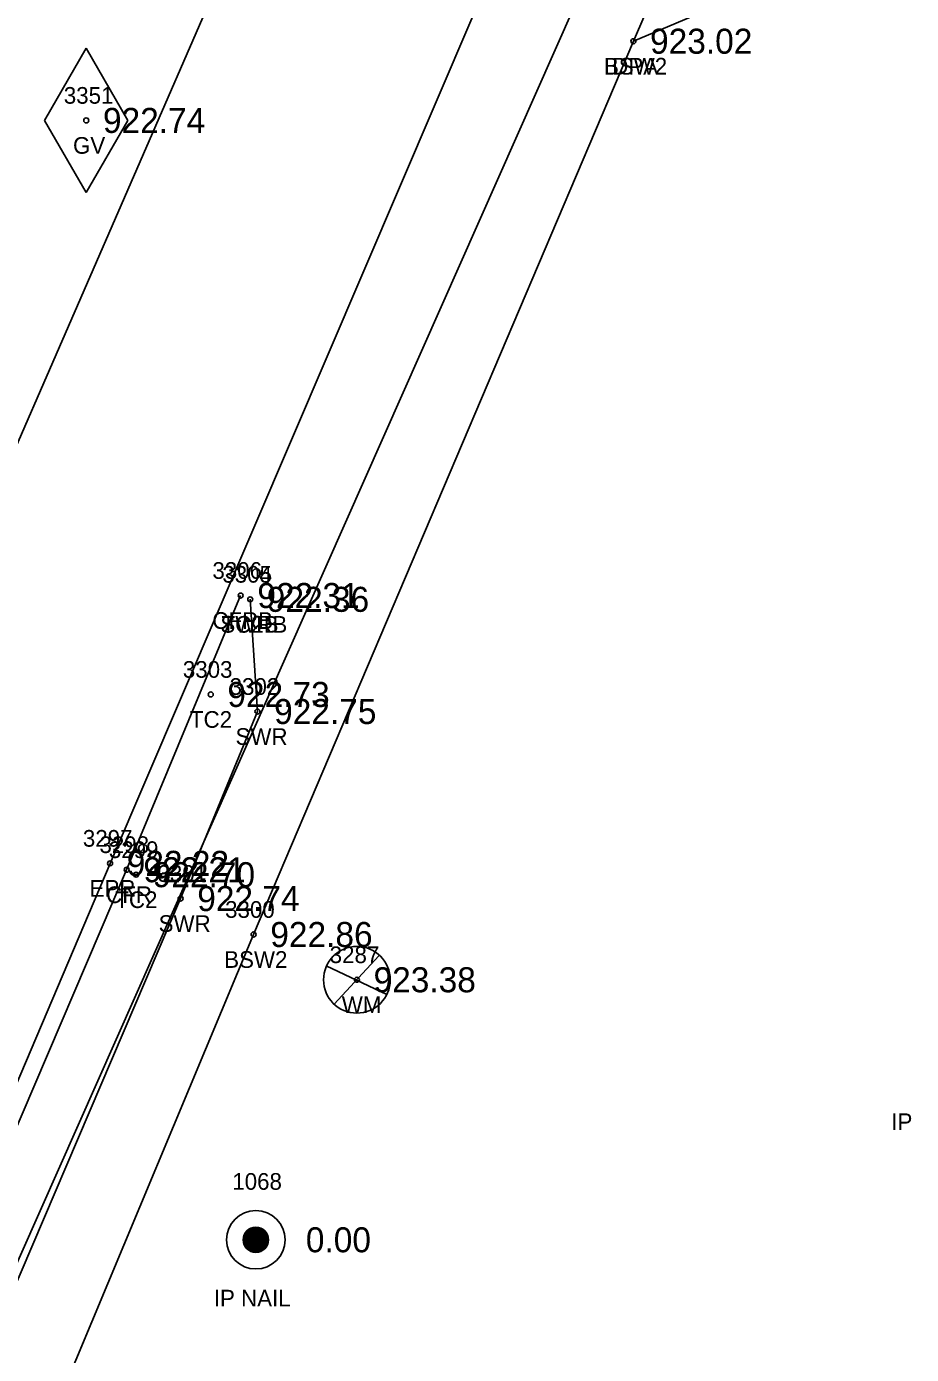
# Model space of a CAD drawing. Extents: x 1575382 to 1578175, y 1099175 to 1101955.
# Drawn here: x 1577161 to 1577214.1, y 1100867.9 to 1100947.5 of the extents above; entities that cross this region are included whole.
import ezdxf

# ---------------------------------------------------------------- set-up
doc = ezdxf.new("R2010")
doc.units = 0
for name, color, linetype in [('RD_EX_Conc', 7, 'Continuous'), ('RD_EX_Conc_txCode', 7, 'Continuous'), ('RD_EX_DR_Pipe', 7, 'Continuous'), ('RD_EX_Driveway', 7, 'Continuous'), ('RD_EX_Driveway_txCode', 7, 'Continuous'), ('RD_EX_DV_Prop_txCode', 7, 'Continuous'), ('RD_EX_DV_PropPin', 7, 'Continuous'), ('RD_EX_Road', 7, 'Continuous'), ('RD_EX_Road_txCode', 7, 'Continuous'), ('RD_EX_TX_Conc_ELEV', 7, 'Continuous'), ('RD_EX_TX_Driveway_ELEV', 7, 'Continuous'), ('RD_EX_TX_DV_Prop_ELEV', 7, 'Continuous'), ('RD_EX_TX_Road_ELEV', 7, 'Continuous'), ('RD_EX_TX_UT_ELEV', 7, 'Continuous'), ('RD_EX_UT', 7, 'Continuous'), ('RD_EX_UT_txCode', 7, 'Continuous'), ('RD_HC_Cl', 7, 'Continuous'), ('RD_SMD_Locator', 7, 'Continuous')]:
    doc.layers.add(name, color=color, linetype=linetype)

msp = doc.modelspace()

# ---------------------------------------------------------------- linework, layer by layer
at = {"layer": 'RD_EX_Conc'}
for points in [[(1577055.154, 1100662.638), (1577085.172, 1100716.01), (1577085.172, 1100716.01), (1577107.371, 1100755.865), (1577118.9, 1100776.662), (1577132.782, 1100800.808), (1577154.825, 1100846.618), (1577163.043, 1100865.238), (1577174.665, 1100893.053), (1577197.436, 1100946.62), (1577213.904, 1100984.916), (1577231.037, 1101024.713)], [(1577129.98, 1100812.481), (1577147.365, 1100850.909), (1577167.052, 1100896.938), (1577173.888, 1100913.381)], [(1577132.717, 1100811.321), (1577150.445, 1100848.795), (1577170.285, 1100895.209), (1577174.895, 1100906.424), (1577174.458, 1100913.152)]]:
    msp.add_lwpolyline(points, dxfattribs=at)
at = {"layer": 'RD_EX_DR_Pipe'}
msp.add_lwpolyline([(1577139.994, 1100787.337), (1577129.779, 1100804.197), (1577129.779, 1100804.197), (1577232.824, 1101036.463), (1577232.824, 1101036.463), (1577240.152, 1101052.982)], dxfattribs=at)
at = {"layer": 'RD_EX_Driveway'}
msp.add_lwpolyline([(1577197.436, 1100946.62), (1577210.609, 1100952.199), (1577244.847, 1100927.029)], dxfattribs=at)
at = {"layer": 'RD_EX_DV_PropPin'}
for p, q in [((1577174.201, 1100874.272), (1577174.201, 1100875.22)), ((1577174.236, 1100874.231), (1577174.236, 1100875.261)), ((1577174.271, 1100874.195), (1577174.271, 1100875.297)), ((1577174.306, 1100874.164), (1577174.306, 1100875.328)), ((1577174.341, 1100874.136), (1577174.341, 1100875.356)), ((1577174.377, 1100874.111), (1577174.377, 1100875.38)), ((1577174.412, 1100874.09), (1577174.412, 1100875.402)), ((1577174.447, 1100874.07), (1577174.447, 1100875.422)), ((1577174.482, 1100874.053), (1577174.482, 1100875.439)), ((1577174.517, 1100874.038), (1577174.517, 1100875.453)), ((1577174.552, 1100874.025), (1577174.552, 1100875.466)), ((1577174.587, 1100874.014), (1577174.587, 1100875.477)), ((1577174.622, 1100874.005), (1577174.622, 1100875.487)), ((1577174.657, 1100873.998), (1577174.657, 1100875.494)), ((1577174.692, 1100873.992), (1577174.692, 1100875.5)), ((1577174.727, 1100873.988), (1577174.727, 1100875.504)), ((1577174.762, 1100873.986), (1577174.762, 1100875.506)), ((1577174.797, 1100873.985), (1577174.797, 1100875.507)), ((1577174.832, 1100873.986), (1577174.832, 1100875.506)), ((1577174.867, 1100873.988), (1577174.867, 1100875.504)), ((1577174.902, 1100873.992), (1577174.902, 1100875.5)), ((1577174.937, 1100873.998), (1577174.937, 1100875.494)), ((1577174.972, 1100874.005), (1577174.972, 1100875.487)), ((1577175.007, 1100874.014), (1577175.007, 1100875.477)), ((1577175.042, 1100874.025), (1577175.042, 1100875.466)), ((1577175.077, 1100874.038), (1577175.077, 1100875.453)), ((1577175.112, 1100874.053), (1577175.112, 1100875.439)), ((1577175.147, 1100874.07), (1577175.147, 1100875.422)), ((1577175.182, 1100874.09), (1577175.182, 1100875.402)), ((1577175.217, 1100874.111), (1577175.217, 1100875.38)), ((1577175.252, 1100874.136), (1577175.252, 1100875.356)), ((1577175.287, 1100874.164), (1577175.287, 1100875.328)), ((1577175.322, 1100874.195), (1577175.322, 1100875.297)), ((1577175.357, 1100874.231), (1577175.357, 1100875.261)), ((1577175.392, 1100874.272), (1577175.392, 1100875.22)), ((1577174.061, 1100874.55), (1577174.061, 1100874.942)), ((1577174.096, 1100874.448), (1577174.096, 1100875.044)), ((1577174.131, 1100874.376), (1577174.131, 1100875.115)), ((1577174.166, 1100874.319), (1577174.166, 1100875.172)), ((1577175.427, 1100874.319), (1577175.427, 1100875.172)), ((1577175.462, 1100874.376), (1577175.462, 1100875.115)), ((1577175.497, 1100874.448), (1577175.497, 1100875.044)), ((1577175.532, 1100874.55), (1577175.532, 1100874.942))]:
    msp.add_line(p, q, dxfattribs=at)
for radius in [1.75, 0.761]:
    msp.add_circle((1577174.797, 1100874.746), radius, dxfattribs=at)
at = {"layer": 'RD_EX_Road'}
msp.add_lwpolyline([(1577078.765, 1100718.331), (1577101.643, 1100758.923), (1577113.339, 1100780.089), (1577125.29, 1100804.69), (1577146.474, 1100851.246), (1577166.057, 1100897.319), (1577205.167, 1100988.676), (1577222.285, 1101028.955), (1577224.552, 1101032.022), (1577228.298, 1101034.471), (1577233.178, 1101036.099), (1577233.178, 1101036.099), (1577237.423, 1101035.839), (1577245.428, 1101032.846), (1577248.283, 1101031.553), (1577256.851, 1101026.156), (1577298.2, 1100997.596), (1577319.207, 1100982.295), (1577334.075, 1100971.377)], dxfattribs=at)
at = {"layer": 'RD_EX_UT'}
for p, q in [((1577162.131, 1100941.871), (1577164.631, 1100946.202)), ((1577164.631, 1100946.202), (1577167.131, 1100941.871)), ((1577162.131, 1100941.871), (1577164.631, 1100937.541)), ((1577164.631, 1100937.541), (1577167.131, 1100941.871)), ((1577179.023, 1100891.175), (1577182.654, 1100889.462)), ((1577179.504, 1100888.88), (1577182.172, 1100891.776))]:
    msp.add_line(p, q, dxfattribs=at)
msp.add_circle((1577180.856, 1100890.338), 2, dxfattribs=at)
at = {"layer": 'RD_HC_Cl'}
msp.add_line((1577114.032, 1100815.757), (1577364.891, 1101392.08), dxfattribs=at)
at = {"layer": 'RD_SMD_Locator'}
for centre in [(1577197.436, 1100946.62), (1577197.436, 1100946.62), (1577164.631, 1100941.871), (1577173.888, 1100913.381), (1577174.458, 1100913.152), (1577174.458, 1100913.152), (1577172.091, 1100907.448), (1577174.895, 1100906.424), (1577166.057, 1100897.319), (1577167.052, 1100896.938), (1577167.616, 1100896.64), (1577170.285, 1100895.209), (1577174.665, 1100893.053), (1577180.856, 1100890.338), (1577174.797, 1100874.746)]:
    msp.add_circle(centre, 0.15, dxfattribs=at)

# ---------------------------------------------------------------- texts
at = {"layer": 'RD_EX_Conc_txCode'}
for s, p in [('BSW2', (1577195.673, 1100944.62)), ('3306', (1577172.195, 1100914.381)), ('3304', (1577172.789, 1100914.152)), ('3305', (1577172.789, 1100914.152)), ('CFRB', (1577172.187, 1100911.381)), ('SWRB', (1577172.671, 1100911.152)), ('TC2B', (1577172.742, 1100911.152)), ('3303', (1577170.422, 1100908.448)), ('3302', (1577173.226, 1100907.424)), ('TC2', (1577170.847, 1100905.448)), ('SWR', (1577173.58, 1100904.424)), ('3298', (1577165.422, 1100897.938)), ('3299', (1577165.986, 1100897.64)), ('3301', (1577168.899, 1100896.209)), ('CFR', (1577165.824, 1100894.938)), ('TC2', (1577166.372, 1100894.64)), ('3300', (1577172.956, 1100894.053)), ('SWR', (1577168.97, 1100893.209)), ('BSW2', (1577172.901, 1100891.053))]:
    msp.add_text(s, height=1, dxfattribs=at).set_placement(p)
at = {"layer": 'RD_EX_Driveway_txCode'}
msp.add_text('DPA', height=1, dxfattribs=at).set_placement((1577196.169, 1100944.62))
at = {"layer": 'RD_EX_DV_Prop_txCode'}
for s, p in [('IP RR SPK', (1577212.902, 1100881.326)), ('1068', (1577173.387, 1100877.746)), ('IP NAIL', (1577172.277, 1100870.746))]:
    msp.add_text(s, height=1, dxfattribs=at).set_placement(p)
at = {"layer": 'RD_EX_Road_txCode'}
for s, p in [('3297', (1577164.427, 1100898.319)), ('EPR', (1577164.829, 1100895.319))]:
    msp.add_text(s, height=1, dxfattribs=at).set_placement(p)
at = {"layer": 'RD_EX_TX_Conc_ELEV'}
for s, p in [('923.02', (1577198.436, 1100945.87)), ('922.31', (1577174.888, 1100912.631)), ('922.36', (1577175.458, 1100912.402)), ('922.36', (1577175.458, 1100912.402)), ('922.73', (1577173.091, 1100906.698)), ('922.75', (1577175.895, 1100905.674)), ('922.21', (1577168.052, 1100896.188)), ('922.70', (1577168.616, 1100895.89)), ('922.74', (1577171.285, 1100894.459)), ('922.86', (1577175.665, 1100892.303))]:
    msp.add_text(s, height=1.5, dxfattribs=at).set_placement(p)
at = {"layer": 'RD_EX_TX_Driveway_ELEV'}
msp.add_text('923.02', height=1.5, dxfattribs=at).set_placement((1577198.436, 1100945.87))
at = {"layer": 'RD_EX_TX_DV_Prop_ELEV'}
msp.add_text('0.00', height=1.5, dxfattribs=at).set_placement((1577177.797, 1100873.996))
at = {"layer": 'RD_EX_TX_Road_ELEV'}
msp.add_text('922.22', height=1.5, dxfattribs=at).set_placement((1577167.057, 1100896.569))
at = {"layer": 'RD_EX_TX_UT_ELEV'}
for s, p in [('922.74', (1577165.631, 1100941.121)), ('923.38', (1577181.856, 1100889.588))]:
    msp.add_text(s, height=1.5, dxfattribs=at).set_placement(p)
at = {"layer": 'RD_EX_UT_txCode'}
for s, p in [('3351', (1577163.284, 1100942.871)), ('GV', (1577163.835, 1100939.871)), ('3287', (1577179.226, 1100891.338)), ('WM', (1577179.951, 1100888.338))]:
    msp.add_text(s, height=1, dxfattribs=at).set_placement(p)

doc.saveas('drawing.dxf')
